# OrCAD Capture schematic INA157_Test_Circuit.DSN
size A; title: INA157: High-Speed, Precision DIFFERENCE AMPLIFIER; rev: 1.1; note: Datasheet: SBOS105  EVM: N/A
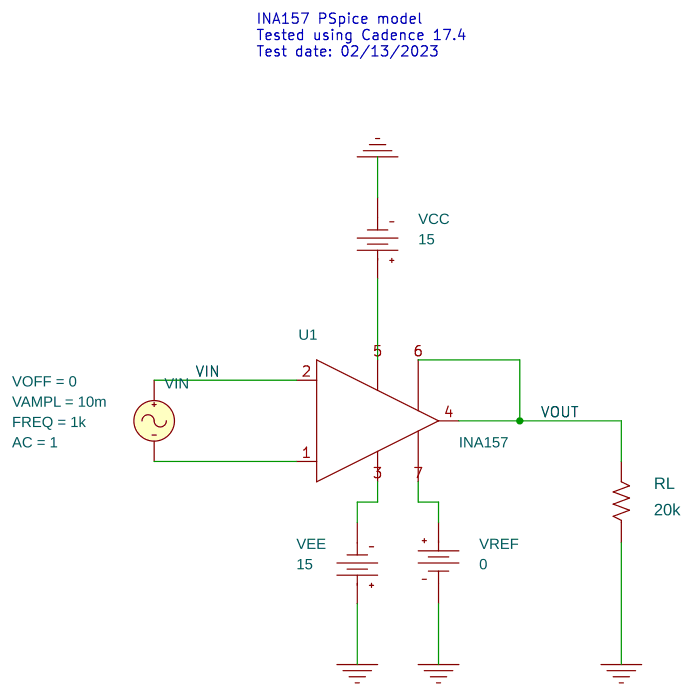
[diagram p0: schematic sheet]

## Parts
RL  20k  [AX/RC05]
U1  INA157
VCC  VDC
VEE  VDC
VIN  VSIN
VREF  VDC

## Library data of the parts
RL = R
U1 = INA157
VCC VEE = VDC: DC: 15
VIN = VSIN: AC: 1; FREQ: 1k; VAMPL: 10m; VOFF: 0
VREF = VDC: DC: 0

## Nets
VIN: U1.2(-) VIN.1(+)
0: RL.1 VCC.1(-) VEE.0(+) VREF.1(-)
VOUT: RL.2 U1.4(OUT) U1.6(SENSE)
N14298623: U1.1(+) VIN.2(-)
N14298647: U1.3(V-) VEE.1(-)
N14298653: U1.7(REF) VREF.0(+)
N14298948: U1.5(V+) VCC.0(+)

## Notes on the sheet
- INA157 PSpice model
  Tested using Cadence 17.4
  Test date: 02/13/2023
